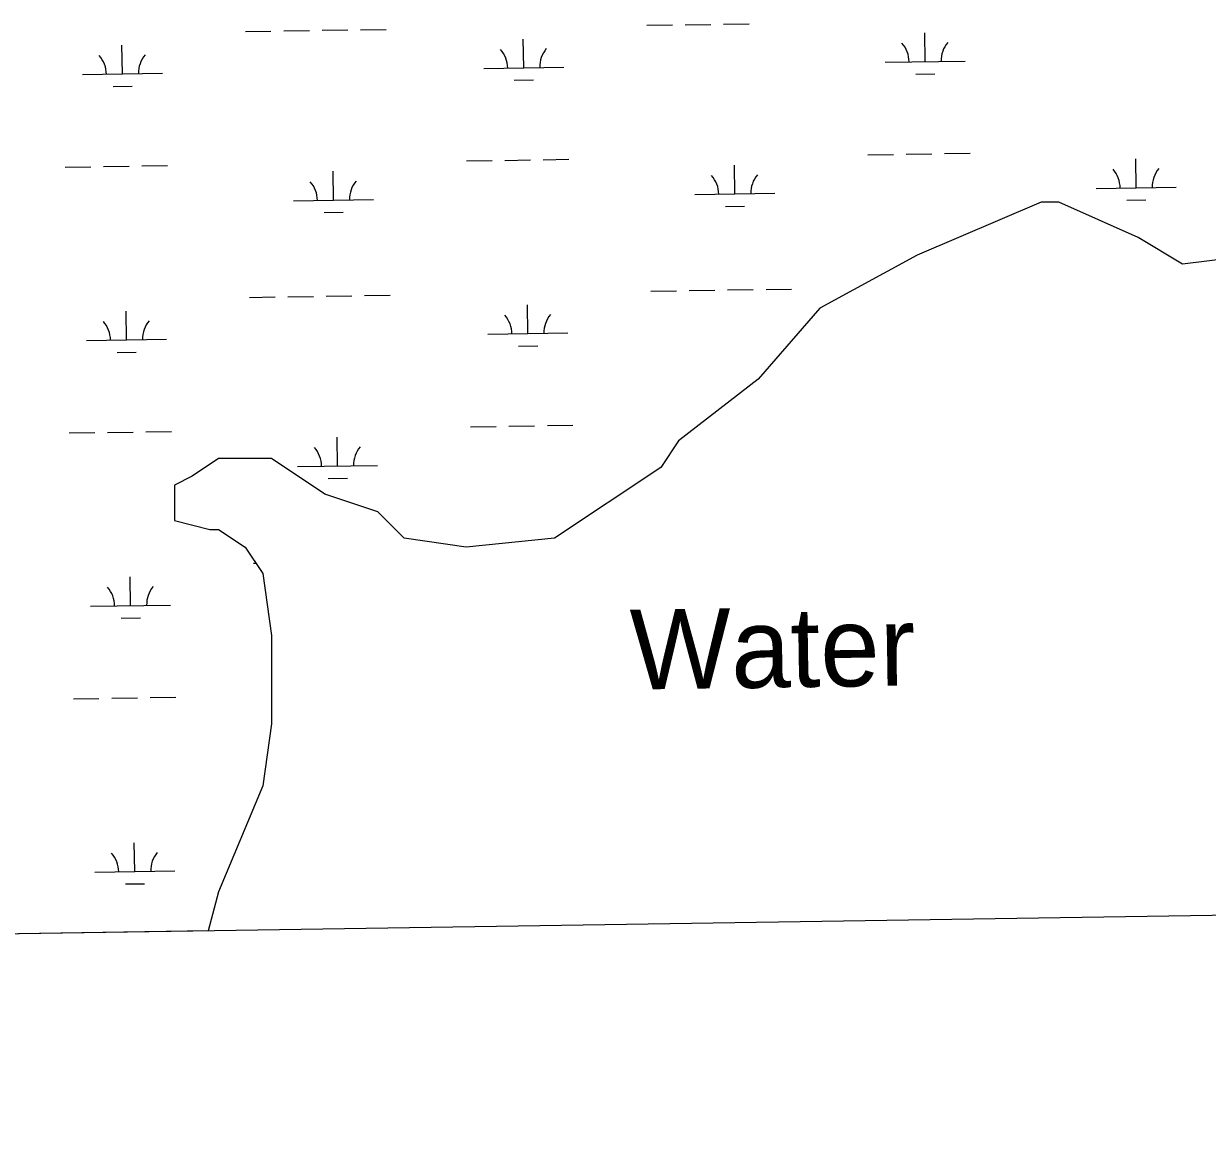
# Model space of a CAD drawing. Extents: x 3823584 to 3861785, y 301729 to 327625.
# Drawn here: x 3844182 to 3845662, y 307156 to 308547 of the extents above; entities that cross this region are included whole.
import ezdxf

# ---------------------------------------------------------------- set-up
doc = ezdxf.new("R2010")
doc.units = 0
for name, color, linetype in [('V-GRID-FRAM', 7, 'Continuous'), ('V-RIVR-IDEN', 7, 'Continuous'), ('V-TOPO-SHOR', 7, 'Continuous'), ('V-WETL-SWMP', 7, 'Continuous')]:
    doc.layers.add(name, color=color, linetype=linetype)

msp = doc.modelspace()

# ---------------------------------------------------------------- linework, layer by layer
at = {"layer": 'V-GRID-FRAM'}
msp.add_lwpolyline([(3827552.2, 325336), (3859397.3, 325827), (3859685.5, 307646.8), (3827824.6, 307155.6), (3827552.2, 325336)], dxfattribs=at)
at = {"layer": 'V-TOPO-SHOR'}
for p, q in [((3845453.8, 308323.2), (3845299, 308256.8)), ((3845475.9, 308323.2), (3845453.8, 308323.2)), ((3845575.4, 308278.9), (3845475.9, 308323.2)), ((3845630.7, 308245.7), (3845575.4, 308278.9)), ((3845299, 308256.8), (3845177.3, 308190.4)), ((3845719.2, 308256.8), (3845630.7, 308245.7)), ((3845177.3, 308190.4), (3845099.9, 308101.9)), ((3845099.9, 308101.9), (3845000.4, 308024.4)), ((3845000.4, 308024.4), (3844978.3, 307991.2)), ((3844425.4, 308002.3), (3844392.2, 307980.2)), ((3844491.7, 308002.3), (3844425.4, 308002.3)), ((3844558.1, 307958), (3844491.7, 308002.3)), ((3844978.3, 307991.2), (3844845.6, 307902.7)), ((3844392.2, 307980.2), (3844370.1, 307969.1)), ((3844370.1, 307969.1), (3844370.1, 307924.8)), ((3844624.4, 307935.9), (3844558.1, 307958)), ((3844657.6, 307902.7), (3844624.4, 307935.9)), ((3844370.1, 307924.8), (3844414.3, 307913.8)), ((3844414.3, 307913.8), (3844425.4, 307913.8)), ((3844425.4, 307913.8), (3844458.5, 307891.6)), ((3844735, 307891.6), (3844657.6, 307902.7)), ((3844845.6, 307902.7), (3844735, 307891.6)), ((3844458.5, 307891.6), (3844480.6, 307858.4)), ((3844480.6, 307858.4), (3844491.7, 307781)), ((3844491.7, 307781), (3844491.7, 307670.3)), ((3844491.7, 307670.3), (3844480.6, 307592.9)), ((3844480.6, 307592.9), (3844425.4, 307460.1)), ((3844425.4, 307460.1), (3844412.4, 307411.4)), ((3844412.4, 307411.4), (3843488.2, 307397.1))]:
    msp.add_line(p, q, dxfattribs=at)
at = {"layer": 'V-WETL-SWMP'}
for p, q in [((3844458.9, 308536.7), (3844490.9, 308537.2)), ((3844506.9, 308537.5), (3844538.9, 308537.9)), ((3844554.9, 308538.2), (3844586.9, 308538.7)), ((3844602.9, 308538.9), (3844634.9, 308539.4)), ((3844960.8, 308544.5), (3844992.8, 308544.9)), ((3845008.8, 308545.2), (3845040.8, 308545.7)), ((3845056.8, 308545.9), (3845088.8, 308546.4)), ((3845308.8, 308499.1), (3845308.3, 308535.1)), ((3844305.1, 308483.6), (3844304.6, 308519.6)), ((3844807, 308491.3), (3844806.4, 308527.3)), ((3844757, 308490.6), (3844857, 308492.1)), ((3845258.8, 308498.3), (3845358.8, 308499.8)), ((3844255.2, 308482.8), (3844355.1, 308484.4)), ((3844795.2, 308475.7), (3844819.2, 308476.1)), ((3845297.1, 308483.5), (3845321.1, 308483.8)), ((3844293.4, 308468), (3844317.4, 308468.4)), ((3844735.4, 308374.8), (3844767.4, 308375.3)), ((3844783.4, 308375.5), (3844815.4, 308376)), ((3844831.4, 308376.3), (3844863.4, 308376.8)), ((3845237.2, 308382.5), (3845269.2, 308383)), ((3845285.2, 308383.3), (3845317.2, 308383.8)), ((3845333.2, 308384), (3845365.2, 308384.5)), ((3845572.7, 308341.3), (3845572.2, 308377.3)), ((3844233.5, 308367), (3844265.5, 308367.5)), ((3844281.5, 308367.8), (3844313.5, 308368.3)), ((3844329.5, 308368.5), (3844361.5, 308369)), ((3844569, 308325.8), (3844568.5, 308361.8)), ((3845070.9, 308333.5), (3845070.3, 308369.5)), ((3845522.7, 308340.5), (3845622.7, 308342)), ((3844519.1, 308325), (3844619, 308326.6)), ((3845020.9, 308332.8), (3845120.9, 308334.3)), ((3845561, 308325.6), (3845585, 308326)), ((3845059.1, 308317.9), (3845083.1, 308318.3)), ((3845453.8, 308323.2), (3845299, 308256.8)), ((3845475.9, 308323.2), (3845453.8, 308323.2)), ((3845575.4, 308278.9), (3845475.9, 308323.2)), ((3844557.3, 308310.2), (3844581.3, 308310.5)), ((3845630.7, 308245.7), (3845575.4, 308278.9)), ((3845299, 308256.8), (3845177.3, 308190.4)), ((3845719.2, 308256.8), (3845630.7, 308245.7)), ((3844965.9, 308211.8), (3844997.9, 308212.3)), ((3845013.9, 308212.6), (3845045.9, 308213.1)), ((3845061.9, 308213.3), (3845093.9, 308213.8)), ((3845109.9, 308214), (3845141.9, 308214.5)), ((3844464.1, 308204.1), (3844496.1, 308204.6)), ((3844512.1, 308204.8), (3844544.1, 308205.3)), ((3844560.1, 308205.6), (3844592, 308206.1)), ((3844608, 308206.3), (3844640, 308206.8)), ((3844812.1, 308158.7), (3844811.6, 308194.7)), ((3844310.3, 308151), (3844309.7, 308187)), ((3845177.3, 308190.4), (3845099.9, 308101.9)), ((3844260.3, 308150.2), (3844360.3, 308151.7)), ((3844762.1, 308157.9), (3844862.1, 308159.5)), ((3844298.5, 308135.3), (3844322.5, 308135.7)), ((3844800.4, 308143.1), (3844824.4, 308143.5)), ((3845099.9, 308101.9), (3845000.4, 308024.4)), ((3844238.7, 308034.4), (3844270.6, 308034.9)), ((3844286.6, 308035.2), (3844318.6, 308035.6)), ((3844334.6, 308035.9), (3844366.6, 308036.4)), ((3844740.5, 308042.1), (3844772.5, 308042.6)), ((3844788.5, 308042.9), (3844820.5, 308043.4)), ((3844836.5, 308043.6), (3844868.5, 308044.1)), ((3844574.2, 307993.1), (3844573.6, 308029.1)), ((3845000.4, 308024.4), (3844978.3, 307991.2)), ((3844425.4, 308002.3), (3844392.2, 307980.2)), ((3844491.7, 308002.3), (3844425.4, 308002.3)), ((3844558.1, 307958), (3844491.7, 308002.3)), ((3844524.2, 307992.4), (3844624.2, 307993.9)), ((3844978.3, 307991.2), (3844845.6, 307902.7)), ((3844392.2, 307980.2), (3844370.1, 307969.1)), ((3844562.4, 307977.5), (3844586.4, 307977.9)), ((3844370.1, 307969.1), (3844370.1, 307924.8)), ((3844624.4, 307935.9), (3844558.1, 307958)), ((3844657.6, 307902.7), (3844624.4, 307935.9)), ((3844370.1, 307924.8), (3844414.3, 307913.8)), ((3844414.3, 307913.8), (3844425.4, 307913.8)), ((3844425.4, 307913.8), (3844458.5, 307891.6)), ((3844735, 307891.6), (3844657.6, 307902.7)), ((3844845.6, 307902.7), (3844735, 307891.6)), ((3844458.5, 307891.6), (3844480.6, 307858.4)), ((3844469.2, 307871.4), (3844472, 307871.5)), ((3844315.4, 307818.3), (3844314.8, 307854.3)), ((3844480.6, 307858.4), (3844491.7, 307781)), ((3844265.4, 307817.6), (3844365.4, 307819.1)), ((3844303.6, 307802.7), (3844327.6, 307803.1)), ((3844491.7, 307781), (3844491.7, 307670.3)), ((3844243.8, 307701.8), (3844275.8, 307702.3)), ((3844291.8, 307702.5), (3844323.8, 307703)), ((3844339.8, 307703.3), (3844371.8, 307703.7)), ((3844491.7, 307670.3), (3844480.6, 307592.9)), ((3844480.6, 307592.9), (3844425.4, 307460.1)), ((3844320.5, 307485.7), (3844320, 307521.7)), ((3844270.5, 307484.9), (3844370.5, 307486.5)), ((3844308.8, 307470.1), (3844332.8, 307470.4)), ((3844425.4, 307460.1), (3844412.4, 307411.4)), ((3844412.4, 307411.4), (3843488.2, 307397.1))]:
    msp.add_line(p, q, dxfattribs=at)
for centre, start, end in [((3845253.6, 308498.7), 0.1115, 41.6552), ((3845364.1, 308500.4), 140.1115, 181.6552), ((3844249.9, 308483.2), 0.1115, 41.6552), ((3844360.4, 308484.9), 140.1115, 181.6552), ((3844751.7, 308491), 0.1115, 41.6552), ((3844862.2, 308492.7), 140.1115, 181.6552), ((3845015.6, 308333.1), 0.1115, 41.6552), ((3845126.1, 308334.8), 140.1115, 181.6552), ((3845517.5, 308340.9), 0.1115, 41.6552), ((3845628, 308342.6), 140.1115, 181.6552), ((3844513.8, 308325.4), 0.1115, 41.6552), ((3844624.3, 308327.1), 140.1115, 181.6552), ((3844756.9, 308158.3), 0.1115, 41.6552), ((3844867.4, 308160), 140.1115, 181.6552), ((3844255, 308150.6), 0.1115, 41.6552), ((3844365.5, 308152.3), 140.1115, 181.6552), ((3844518.9, 307992.8), 0.1115, 41.6552), ((3844629.4, 307994.5), 140.1115, 181.6552), ((3844260.2, 307817.9), 0.1115, 41.6552), ((3844370.6, 307819.7), 140.1115, 181.6552), ((3844265.3, 307485.3), 0.1115, 41.6552), ((3844375.8, 307487), 140.1115, 181.6552)]:
    msp.add_arc(centre, 35.2, start, end, dxfattribs=at)

# ---------------------------------------------------------------- texts
at = {"layer": 'V-RIVR-IDEN'}
msp.add_text('Water', height=100, rotation=0.8425, dxfattribs=at).set_placement((3844940.6, 307713.3))

doc.saveas('drawing.dxf')
